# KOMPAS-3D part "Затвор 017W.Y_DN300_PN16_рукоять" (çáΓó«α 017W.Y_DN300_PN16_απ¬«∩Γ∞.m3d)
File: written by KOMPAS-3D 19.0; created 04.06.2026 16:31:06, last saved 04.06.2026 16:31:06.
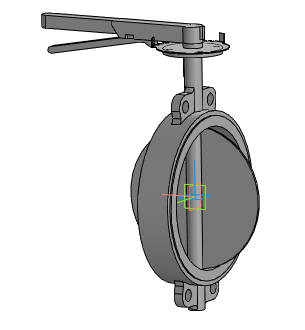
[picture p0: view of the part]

Document properties: Автор: Энергия; Полное имя файла: ..\..\..\3d для проектировщиков\017W разные\x.x Тип 017W.Y(S) Затвор дисковый поворотный межфланцевый\Затвор 017W.Y(S)_DN32-DN350_рукоять\Затвор 017W.Y_DN300_PN16_рукоять.a3d

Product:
- Part/product: Затвор 017W.Y_DN300_PN16_рукоять
    Масса: 32.0677

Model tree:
1. Операция без истории:1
